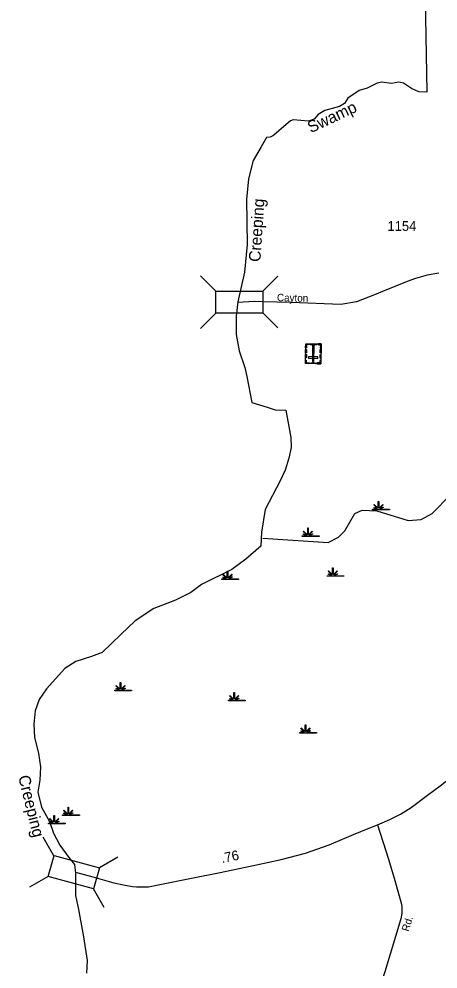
# Model space of a CAD drawing. Extents: x 2532689 to 2764727, y 536648 to 732970.
# Drawn here: x 2538542 to 2543928, y 614847 to 627049 of the extents above; entities that cross this region are included whole.
import ezdxf

# ---------------------------------------------------------------- set-up
doc = ezdxf.new("R2010")
doc.units = 0
for name, color, linetype in [('Exist Boundary Political CountyLine', 7, 'Continuous'), ('Exist Cultural Cemetery CELL', 7, 'Continuous'), ('Exist Hydrographic Creek Single Shore', 7, 'Continuous'), ('Exist Hydrographic Swamp CELL', 7, 'Continuous'), ('Exist Hydrographic Swamp Label', 7, 'Continuous'), ('Exist Road Primary NC Attributed', 7, 'Continuous'), ('Exist Road Primary NC Mileage Hundredths English Label', 7, 'Continuous'), ('Exist Road Primary NC Structure Standard Bridge CELL', 7, 'Continuous'), ('Exist Road Secondary Structure Standard Bridge CELL', 7, 'Continuous'), ('Exist Road Secondary Type 51 Attributed', 7, 'Continuous'), ('Exist Road Secondary Type 51 Label', 7, 'Continuous'), ('Exist Road Secondary Type 51 Number Label', 7, 'Continuous')]:
    doc.layers.add(name, color=color, linetype=linetype)

msp = doc.modelspace()

# ---------------------------------------------------------------- linework, layer by layer
at = {"layer": 'Exist Boundary Political CountyLine'}
for points in [[(2545530, 640820), (2543696, 636565), (2543601, 636432), (2543784, 626108)], [(2543784, 626108), (2543682, 626112), (2543589, 626157), (2543483, 626223), (2543423, 626238), (2543329, 626220), (2543206, 626239), (2543148, 626227), (2543018, 626159), (2542914, 626132), (2542768, 626031), (2542727, 625962), (2542660, 625926), (2542474, 625876), (2542389, 625821), (2542335, 625763), (2542262, 625736), (2542066, 625756), (2542033, 625743), (2541978, 625695), (2541818, 625559), (2541807, 625547), (2541771, 625530), (2541722, 625527), (2541653, 625409), (2541552, 625231), (2541494, 624998), (2541465, 624732), (2541474, 624152), (2541442, 623798), (2541354, 623417), (2541335, 623231), (2541335, 622997), (2541373, 622789), (2541446, 622571), (2541471, 622457), (2541534, 622125), (2541733, 622065), (2541837, 622030), (2541970, 622024), (2542035, 621672), (2542042, 621546), (2542012, 621408), (2541965, 621253), (2541901, 621116), (2541706, 620750), (2541658, 620457), (2541649, 620279), (2541456, 620112), (2541276, 619980), (2540886, 619787), (2540750, 619681), (2540553, 619583), (2540275, 619478), (2540036, 619318), (2539852, 619142), (2539610, 618914), (2539475, 618860), (2539272, 618798), (2539132, 618707), (2538894, 618447), (2538803, 618309), (2538749, 618164), (2538733, 617992), (2538742, 617826), (2538792, 617617), (2538817, 617445), (2538808, 617273), (2538784, 617119), (2538832, 616926), (2538933, 616740), (2538984, 616591), (2539067, 616438), (2539182, 616280), (2539256, 616188), (2539268, 616078), (2539269, 615790), (2539306, 615612), (2539373, 615262), (2539416, 614958), (2539411, 614794)]]:
    msp.add_lwpolyline(points, dxfattribs=at)
at = {"layer": 'Exist Cultural Cemetery CELL'}
for points in [[(2542422, 622620), (2542223, 622624), (2542228, 622879), (2542427, 622875)], [(2542238, 622806), (2542237, 622763), (2542226, 622763), (2542226, 622806)], [(2542261, 622878), (2542261, 622866), (2542239, 622867), (2542238, 622826), (2542227, 622827), (2542228, 622879)], [(2542369, 622864), (2542284, 622866), (2542285, 622877), (2542369, 622876)], [(2542313, 622651), (2542332, 622651), (2542336, 622854), (2542317, 622854)], [(2542394, 622875), (2542394, 622864), (2542416, 622863), (2542415, 622823), (2542426, 622823), (2542427, 622875)], [(2542426, 622805), (2542425, 622761), (2542413, 622762), (2542414, 622805)], [(2542224, 622667), (2542235, 622667), (2542234, 622635), (2542275, 622634), (2542275, 622623), (2542223, 622624)], [(2542236, 622740), (2542236, 622697), (2542224, 622697), (2542225, 622740)], [(2542382, 622689), (2542383, 622708), (2542265, 622710), (2542265, 622691)], [(2542424, 622737), (2542423, 622694), (2542412, 622694), (2542413, 622738)], [(2542348, 622621), (2542296, 622623), (2542296, 622634), (2542348, 622633)], [(2542423, 622663), (2542411, 622664), (2542411, 622631), (2542370, 622632), (2542370, 622621), (2542422, 622620)]]:
    msp.add_lwpolyline(points, close=True, dxfattribs=at)
at = {"layer": 'Exist Hydrographic Creek Single Shore'}
msp.add_lwpolyline([(2541675, 620382), (2542518, 620324), (2542650, 620392), (2542732, 620477), (2542861, 620696), (2542952, 620739), (2543144, 620733), (2543546, 620609), (2543713, 620619), (2543853, 620696), (2544090, 620936), (2544148, 620961)], dxfattribs=at)
at = {"layer": 'Exist Hydrographic Swamp CELL'}
for points in [[(2543088, 620753), (2543141, 620753), (2543143, 620757), (2543105, 620771), (2543108, 620777), (2543145, 620761), (2543147, 620764), (2543102, 620808), (2543108, 620813), (2543153, 620768), (2543159, 620770), (2543159, 620853), (2543166, 620853), (2543166, 620770), (2543173, 620768), (2543218, 620813), (2543223, 620808), (2543179, 620764), (2543181, 620760), (2543222, 620779), (2543224, 620774), (2543183, 620756), (2543185, 620753), (2543306, 620753), (2543306, 620746), (2543088, 620746)], [(2542182, 620412), (2542235, 620412), (2542237, 620415), (2542198, 620430), (2542201, 620435), (2542239, 620419), (2542241, 620422), (2542196, 620467), (2542201, 620472), (2542247, 620427), (2542253, 620429), (2542253, 620512), (2542260, 620512), (2542260, 620429), (2542266, 620427), (2542312, 620472), (2542317, 620467), (2542272, 620422), (2542274, 620419), (2542315, 620437), (2542318, 620432), (2542277, 620415), (2542278, 620412), (2542400, 620412), (2542400, 620404), (2542182, 620404)], [(2542502, 619899), (2542554, 619899), (2542556, 619903), (2542518, 619918), (2542521, 619923), (2542559, 619907), (2542560, 619910), (2542516, 619955), (2542521, 619960), (2542566, 619914), (2542573, 619917), (2542573, 620000), (2542580, 620000), (2542580, 619917), (2542586, 619914), (2542632, 619960), (2542637, 619955), (2542592, 619910), (2542594, 619907), (2542635, 619925), (2542638, 619920), (2542597, 619902), (2542598, 619899), (2542719, 619899), (2542719, 619892), (2542502, 619892)], [(2541148, 619857), (2541200, 619857), (2541202, 619860), (2541164, 619875), (2541167, 619880), (2541205, 619865), (2541206, 619868), (2541162, 619912), (2541167, 619917), (2541212, 619872), (2541219, 619874), (2541219, 619957), (2541226, 619957), (2541226, 619874), (2541232, 619872), (2541278, 619917), (2541283, 619912), (2541238, 619868), (2541240, 619864), (2541281, 619883), (2541284, 619878), (2541243, 619860), (2541244, 619857), (2541365, 619857), (2541365, 619850), (2541148, 619850)], [(2539772, 618427), (2539825, 618427), (2539827, 618431), (2539789, 618446), (2539792, 618451), (2539829, 618435), (2539831, 618438), (2539787, 618483), (2539792, 618488), (2539837, 618442), (2539843, 618445), (2539843, 618528), (2539851, 618528), (2539851, 618445), (2539857, 618442), (2539902, 618488), (2539907, 618483), (2539863, 618438), (2539865, 618434), (2539906, 618453), (2539908, 618448), (2539867, 618430), (2539869, 618427), (2539990, 618427), (2539990, 618420), (2539772, 618420)], [(2541233, 618299), (2541286, 618299), (2541288, 618303), (2541249, 618318), (2541252, 618323), (2541290, 618307), (2541292, 618310), (2541247, 618355), (2541252, 618360), (2541298, 618314), (2541304, 618317), (2541304, 618400), (2541311, 618400), (2541311, 618317), (2541318, 618314), (2541363, 618360), (2541368, 618355), (2541324, 618310), (2541326, 618306), (2541366, 618325), (2541369, 618320), (2541328, 618302), (2541330, 618299), (2541451, 618299), (2541451, 618292), (2541233, 618292)], [(2542150, 617883), (2542203, 617883), (2542205, 617887), (2542166, 617902), (2542169, 617907), (2542207, 617891), (2542209, 617894), (2542164, 617938), (2542169, 617944), (2542215, 617898), (2542221, 617900), (2542221, 617984), (2542228, 617984), (2542228, 617900), (2542234, 617898), (2542280, 617944), (2542285, 617938), (2542241, 617894), (2542243, 617890), (2542283, 617909), (2542286, 617904), (2542245, 617886), (2542246, 617883), (2542368, 617883), (2542368, 617876), (2542150, 617876)], [(2538919, 616720), (2538972, 616720), (2538974, 616724), (2538936, 616739), (2538939, 616744), (2538976, 616728), (2538978, 616731), (2538934, 616776), (2538939, 616781), (2538984, 616735), (2538990, 616738), (2538990, 616821), (2538998, 616821), (2538998, 616738), (2539004, 616735), (2539049, 616781), (2539054, 616776), (2539010, 616731), (2539012, 616727), (2539053, 616746), (2539055, 616741), (2539014, 616723), (2539016, 616720), (2539137, 616720), (2539137, 616713), (2538919, 616713)], [(2539101, 616827), (2539153, 616827), (2539155, 616831), (2539117, 616845), (2539120, 616851), (2539158, 616835), (2539159, 616838), (2539115, 616882), (2539120, 616887), (2539165, 616842), (2539172, 616844), (2539172, 616927), (2539179, 616927), (2539179, 616844), (2539185, 616842), (2539230, 616887), (2539236, 616882), (2539191, 616838), (2539193, 616834), (2539234, 616853), (2539236, 616848), (2539196, 616830), (2539197, 616827), (2539318, 616827), (2539318, 616820), (2539101, 616820)]]:
    msp.add_lwpolyline(points, close=True, dxfattribs=at)
at = {"layer": 'Exist Road Primary NC Attributed'}
for points in [[(2543150, 616699), (2543308, 616769), (2543447, 616836), (2543583, 616922), (2543795, 617080), (2543956, 617199), (2544018, 617248), (2544283, 617450), (2544522, 617620), (2544757, 617798), (2544930, 617925), (2545091, 618042), (2545260, 618136), (2545395, 618191), (2545550, 618246), (2545692, 618287), (2545807, 618315), (2545839, 618323)], [(2539266, 616093), (2539491, 616032), (2539763, 615956), (2539886, 615927), (2539999, 615906), (2540051, 615904), (2540205, 615903), (2540395, 615940), (2540760, 616014), (2541127, 616087), (2541597, 616185), (2541914, 616255), (2542225, 616333), (2542528, 616444), (2542842, 616575), (2543053, 616662), (2543150, 616699)]]:
    msp.add_lwpolyline(points, dxfattribs=at)
at = {"layer": 'Exist Road Primary NC Structure Standard Bridge CELL'}
for p, q in [((2538990, 616302), (2538853, 616542)), ((2539814, 616285), (2539575, 616148)), ((2538918, 616036), (2538678, 615899)), ((2539637, 615636), (2539500, 615876))]:
    msp.add_line(p, q, dxfattribs=at)
msp.add_lwpolyline([(2539500, 615876), (2538917, 616035), (2538992, 616307), (2539575, 616148)], close=True, dxfattribs=at)
at = {"layer": 'Exist Road Secondary Structure Standard Bridge CELL'}
for p, q in [((2540876, 623749), (2541071, 623554)), ((2541675, 623552), (2541870, 623747)), ((2541675, 623276), (2541870, 623081)), ((2540876, 623076), (2541071, 623271))]:
    msp.add_line(p, q, dxfattribs=at)
msp.add_lwpolyline([(2541071, 623554), (2541675, 623554), (2541675, 623271), (2541071, 623271)], close=True, dxfattribs=at)
at = {"layer": 'Exist Road Secondary Type 51 Attributed'}
for points in [[(2543939, 623783), (2543790, 623760), (2543639, 623718), (2543531, 623677), (2543214, 623548), (2543134, 623517), (2543036, 623476), (2542879, 623418), (2542680, 623383), (2542041, 623408), (2541680, 623416), (2541564, 623419), (2541353, 623408)], [(2543150, 616699), (2543290, 616259), (2543373, 615983), (2543457, 615682), (2543464, 615643), (2543464, 615560), (2543450, 615492), (2543245, 614810), (2542985, 614021), (2542793, 613366), (2542730, 613151), (2542695, 613050), (2542647, 612948), (2542581, 612823), (2542383, 612475), (2542304, 612334), (2542195, 612144), (2542101, 611979), (2542047, 611878), (2541817, 611465), (2541505, 610911)]]:
    msp.add_lwpolyline(points, dxfattribs=at)

# ---------------------------------------------------------------- texts
at = {"layer": 'Exist Hydrographic Swamp Label'}
for s, rotation, p in [('Swamp', 25.1387, (2542294, 625581)), ('Creeping', 86.1959, (2541644, 623926)), ('Creeping', 283.9226, (2538530, 617317))]:
    msp.add_text(s, height=150, rotation=rotation, dxfattribs=at).set_placement(p)
at = {"layer": 'Exist Road Primary NC Mileage Hundredths English Label'}
msp.add_text('.76', height=125, rotation=11.1967, dxfattribs=at).set_placement((2541151, 616208))
at = {"layer": 'Exist Road Secondary Type 51 Label'}
for s, rotation, p in [('Cayton', 358.8658, (2541857, 623425)), ('Rd.', 72.4637, (2543549, 615322))]:
    msp.add_text(s, height=95, rotation=rotation, dxfattribs=at).set_placement(p)
at = {"layer": 'Exist Road Secondary Type 51 Number Label'}
msp.add_text('1154', height=125, dxfattribs=at).set_placement((2543278, 624328))

doc.saveas('drawing.dxf')
